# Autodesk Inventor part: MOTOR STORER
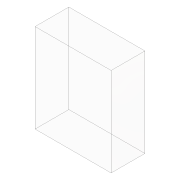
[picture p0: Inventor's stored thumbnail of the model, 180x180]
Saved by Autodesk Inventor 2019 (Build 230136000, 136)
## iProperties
Created: 2019-10
Part Number: MOTOR STORER
Material: PET Plastic
Document SubType Name: Modeling
Designer: hp
Density: 1.541 g/cm^3
Appearance: Polycarbonate - Clear
Author: hp
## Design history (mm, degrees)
sketch "Sketch1"
  geometry: 1 further point
extrude "Extrusion1" new body sketch "Sketch1" distance "d2" = 70; taper "d3" = 0 deg
sketch "Sketch2"
  geometry: L1 (-176.23, 37.96)-(3.77, 37.96); L2 (3.77, 37.96)-(3.77, -172.04); L3 (3.77, -172.04)-(-176.23, -172.04); L4 (-176.23, -172.04)-(-176.23, 37.96); 1 further point
  constraints: 8 end point, 2 parallel, 1 horizontal, 1 perpendicular
  dimensions: "d17" = 180 distance of L2.end L3.end; "d18" = 210 distance of L1.end L2.end
extrude "Extrusion2" join sketch "Sketch2" distance "d8" = 80; taper "d9" = 0 deg
body "Solid1"
